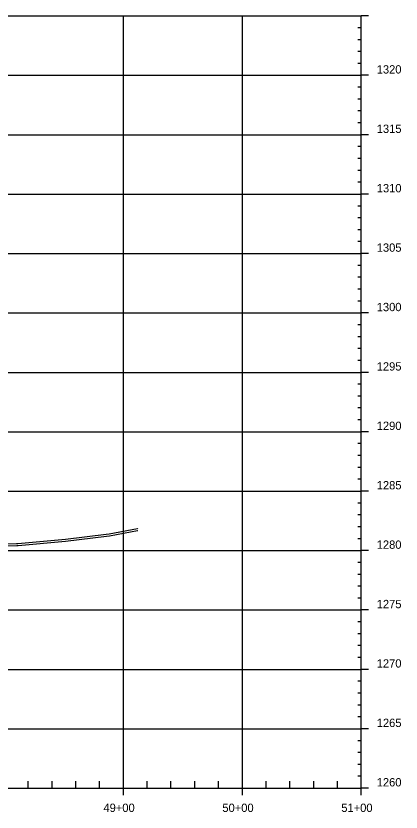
# Model space of a CAD drawing. Extents: x 670877 to 686811, y 705985 to 708501.
# Drawn here: x 686283 to 686606, y 707018 to 707688 of the extents above; entities that cross this region are included whole.
import ezdxf

# ---------------------------------------------------------------- set-up
doc = ezdxf.new("R2010")
doc.units = 0
for name, color, linetype in [('30', 7, 'Continuous'), ('37', 7, 'Continuous'), ('DRAINAGE_HGL LEFT', 7, 'Continuous'), ('R_Exist Surface', 7, 'Continuous')]:
    doc.layers.add(name, color=color, linetype=linetype)

msp = doc.modelspace()

# ---------------------------------------------------------------- linework, layer by layer
at = {"layer": '37'}
for p, q in [((684473.03, 707688.43), (686573.03, 707688.43)), ((686373.03, 707038.43), (686373.03, 707688.43)), ((686473.03, 707038.43), (686473.03, 707688.43)), ((686573.03, 707038.43), (686573.03, 707688.43)), ((686579.03, 707688.43), (686573.03, 707688.43)), ((686573.03, 707678.43), (686570.03, 707678.43)), ((686573.03, 707668.43), (686570.03, 707668.43)), ((686573.03, 707658.43), (686570.03, 707658.43)), ((686573.03, 707648.43), (686570.03, 707648.43)), ((684473.03, 707638.43), (686573.03, 707638.43)), ((686579.03, 707638.43), (686573.03, 707638.43)), ((686573.03, 707628.43), (686570.03, 707628.43)), ((686573.03, 707618.43), (686570.03, 707618.43)), ((686573.03, 707608.43), (686570.03, 707608.43)), ((686573.03, 707598.43), (686570.03, 707598.43)), ((684473.03, 707588.43), (686573.03, 707588.43)), ((686579.03, 707588.43), (686573.03, 707588.43)), ((686573.03, 707578.43), (686570.03, 707578.43)), ((686573.03, 707568.43), (686570.03, 707568.43)), ((686573.03, 707558.43), (686570.03, 707558.43)), ((686573.03, 707548.43), (686570.03, 707548.43)), ((684473.03, 707538.43), (686573.03, 707538.43)), ((686579.03, 707538.43), (686573.03, 707538.43)), ((686573.03, 707528.43), (686570.03, 707528.43)), ((686573.03, 707518.43), (686570.03, 707518.43)), ((686573.03, 707508.43), (686570.03, 707508.43)), ((686573.03, 707498.43), (686570.03, 707498.43)), ((684473.03, 707488.43), (686573.03, 707488.43)), ((686579.03, 707488.43), (686573.03, 707488.43)), ((686573.03, 707478.43), (686570.03, 707478.43)), ((686573.03, 707468.43), (686570.03, 707468.43)), ((686573.03, 707458.43), (686570.03, 707458.43)), ((686573.03, 707448.43), (686570.03, 707448.43)), ((684473.03, 707438.43), (686573.03, 707438.43)), ((686579.03, 707438.43), (686573.03, 707438.43)), ((686573.03, 707428.43), (686570.03, 707428.43)), ((686573.03, 707418.43), (686570.03, 707418.43)), ((686573.03, 707408.43), (686570.03, 707408.43)), ((686573.03, 707398.43), (686570.03, 707398.43)), ((684473.03, 707388.43), (686573.03, 707388.43)), ((686579.03, 707388.43), (686573.03, 707388.43)), ((686573.03, 707378.43), (686570.03, 707378.43)), ((686573.03, 707368.43), (686570.03, 707368.43)), ((686573.03, 707358.43), (686570.03, 707358.43)), ((686573.03, 707348.43), (686570.03, 707348.43)), ((684473.03, 707338.43), (686573.03, 707338.43)), ((686579.03, 707338.43), (686573.03, 707338.43)), ((686573.03, 707328.43), (686570.03, 707328.43)), ((686573.03, 707318.43), (686570.03, 707318.43)), ((686573.03, 707308.43), (686570.03, 707308.43)), ((686573.03, 707298.43), (686570.03, 707298.43)), ((684473.03, 707288.43), (686573.03, 707288.43)), ((686579.03, 707288.43), (686573.03, 707288.43)), ((686573.03, 707278.43), (686570.03, 707278.43)), ((686573.03, 707268.43), (686570.03, 707268.43)), ((686573.03, 707258.43), (686570.03, 707258.43)), ((686573.03, 707248.43), (686570.03, 707248.43)), ((684473.03, 707238.43), (686573.03, 707238.43)), ((686579.03, 707238.43), (686573.03, 707238.43)), ((686573.03, 707228.43), (686570.03, 707228.43)), ((686573.03, 707218.43), (686570.03, 707218.43)), ((686573.03, 707208.43), (686570.03, 707208.43)), ((686573.03, 707198.43), (686570.03, 707198.43)), ((684473.03, 707188.43), (686573.03, 707188.43)), ((686579.03, 707188.43), (686573.03, 707188.43)), ((686573.03, 707178.43), (686570.03, 707178.43)), ((686573.03, 707168.43), (686570.03, 707168.43)), ((686573.03, 707158.43), (686570.03, 707158.43)), ((686573.03, 707148.43), (686570.03, 707148.43)), ((684473.03, 707138.43), (686573.03, 707138.43)), ((686579.03, 707138.43), (686573.03, 707138.43)), ((686573.03, 707128.43), (686570.03, 707128.43)), ((686573.03, 707118.43), (686570.03, 707118.43)), ((686573.03, 707108.43), (686570.03, 707108.43)), ((686573.03, 707098.43), (686570.03, 707098.43)), ((684473.03, 707088.43), (686573.03, 707088.43)), ((686579.03, 707088.43), (686573.03, 707088.43)), ((686573.03, 707078.43), (686570.03, 707078.43)), ((686573.03, 707068.43), (686570.03, 707068.43)), ((686573.03, 707058.43), (686570.03, 707058.43)), ((686293.03, 707038.43), (686293.03, 707044.43)), ((686313.03, 707038.43), (686313.03, 707044.43)), ((686333.03, 707038.43), (686333.03, 707044.43)), ((686353.03, 707038.43), (686353.03, 707044.43)), ((686393.03, 707038.43), (686393.03, 707044.43)), ((686413.03, 707038.43), (686413.03, 707044.43)), ((686433.03, 707038.43), (686433.03, 707044.43)), ((686453.03, 707038.43), (686453.03, 707044.43)), ((686493.03, 707038.43), (686493.03, 707044.43)), ((686513.03, 707038.43), (686513.03, 707044.43)), ((686533.03, 707038.43), (686533.03, 707044.43)), ((686553.03, 707038.43), (686553.03, 707044.43)), ((686573.03, 707048.43), (686570.03, 707048.43)), ((684473.03, 707038.43), (686573.03, 707038.43)), ((686373.03, 707032.43), (686373.03, 707038.43)), ((686473.03, 707032.43), (686473.03, 707038.43)), ((686579.03, 707038.43), (686573.03, 707038.43)), ((686573.03, 707032.43), (686573.03, 707038.43))]:
    msp.add_line(p, q, dxfattribs=at)
at = {"layer": 'DRAINAGE_HGL LEFT'}
msp.add_lwpolyline([(686235.19, 707243.3), (686283.18, 707244.26), (686284.23, 707244.36), (686324.23, 707248.08), (686358.62, 707252.28), (686361.01, 707252.61), (686384.94, 707256.9), (686385.26, 707256.85)], dxfattribs=at)
at = {"layer": 'R_Exist Surface'}
msp.add_lwpolyline([(686235.24, 707241.63), (686283.28, 707242.59), (686284.39, 707242.7), (686324.41, 707246.42), (686358.84, 707250.63), (686361.27, 707250.96), (686384.98, 707255.21), (686385.04, 707255.2)], dxfattribs=at)

# ---------------------------------------------------------------- texts
at = {"layer": '30'}
for s, p in [('1320', (686586.03, 707639.93)), ('1315', (686586.03, 707589.93)), ('1310', (686586.03, 707539.93)), ('1305', (686586.03, 707489.93)), ('1300', (686586.03, 707439.93)), ('1295', (686586.03, 707389.93)), ('1290', (686586.03, 707339.93)), ('1285', (686586.03, 707289.93)), ('1280', (686586.03, 707239.93)), ('1275', (686586.03, 707189.93)), ('1270', (686586.03, 707139.93)), ('1265', (686586.03, 707089.93)), ('1260', (686586.03, 707039.93)), ('49+00', (686356.22, 707018.43)), ('50+00', (686456.22, 707018.43)), ('51+00', (686556.22, 707018.43))]:
    msp.add_text(s, height=7, dxfattribs=at).set_placement(p)

doc.saveas('drawing.dxf')
